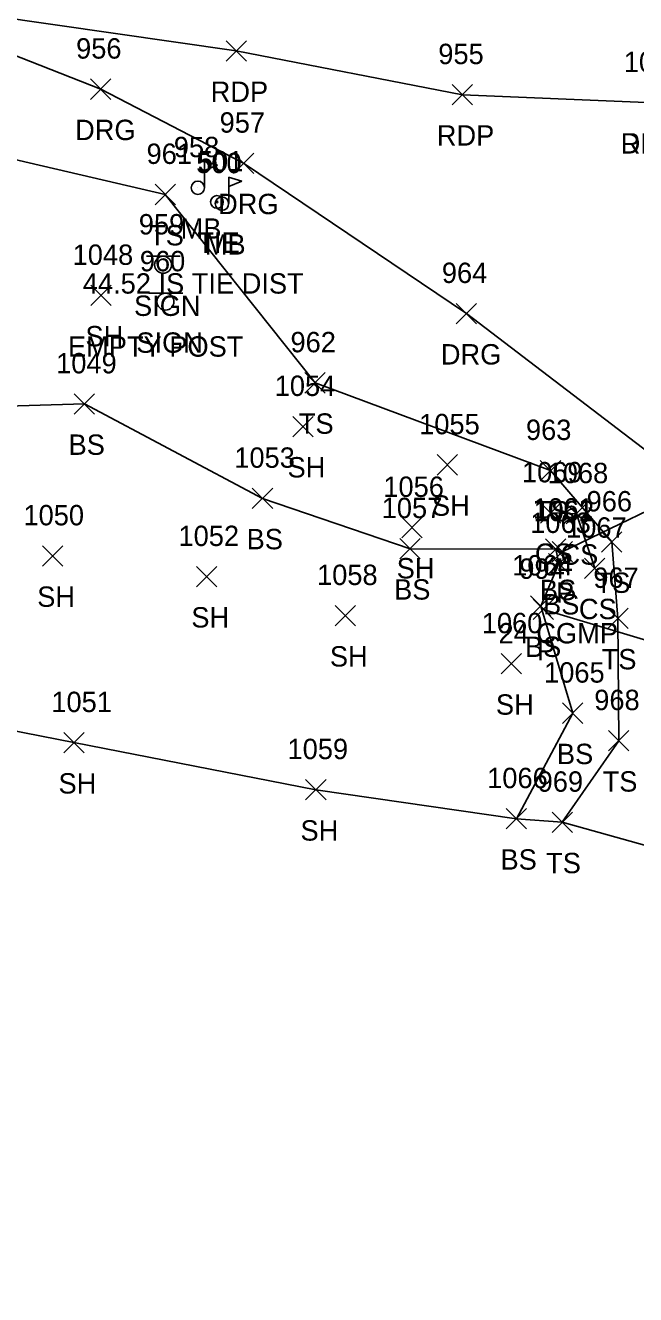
# Model space of a CAD drawing. Extents: x 1679360 to 1685861, y 903420 to 905946.
# Drawn here: x 1679676.5 to 1679736.4, y 903897.6 to 904022.2 of the extents above; entities that cross this region are included whole.
import ezdxf

# ---------------------------------------------------------------- set-up
doc = ezdxf.new("R2010")
doc.units = 0
for name, color, linetype in [('C_A', 7, 'Continuous'), ('C_C', 7, 'Continuous'), ('C_I', 7, 'Continuous'), ('CBP', 7, 'Continuous'), ('D_A', 7, 'Continuous'), ('D_C', 7, 'Continuous'), ('D_I', 7, 'Continuous'), ('D_TIC', 7, 'Continuous'), ('DCP', 7, 'Continuous'), ('L_A', 7, 'Continuous'), ('L_I', 7, 'Continuous'), ('L_TIC', 7, 'Continuous'), ('LELB', 7, 'Continuous'), ('LMB', 7, 'Continuous'), ('LSOGP', 7, 'Continuous'), ('P_A', 7, 'Continuous'), ('P_I', 7, 'Continuous'), ('P_TIC', 7, 'Continuous'), ('PET', 7, 'Continuous'), ('R_A', 7, 'Continuous'), ('R_I', 7, 'Continuous'), ('R_TIC', 7, 'Continuous'), ('RDG', 7, 'Continuous'), ('S_A', 7, 'Continuous'), ('S_C', 7, 'Continuous'), ('S_I', 7, 'Continuous'), ('SSGN', 7, 'Continuous')]:
    doc.layers.add(name, color=color, linetype=linetype)

msp = doc.modelspace()

# ---------------------------------------------------------------- linework, layer by layer
at = {"layer": 'CBP'}
for radius in [0.625, 0.0833]:
    msp.add_circle((1679695.3, 904004.87), radius, dxfattribs=at)
at = {"layer": 'D_TIC'}
for points in [[(1679728.23, 903969.53), (1679730.23, 903971.53)], [(1679730.23, 903969.53), (1679728.23, 903971.53)], [(1679726.37, 903963.87), (1679728.37, 903965.87)], [(1679728.37, 903963.87), (1679726.37, 903965.87)]]:
    msp.add_lwpolyline(points, dxfattribs=at)
at = {"layer": 'DCP'}
for points in [[(1679729.23, 903970.53), (1679771.57, 903990.95)], [(1679765.8, 903953.34), (1679727.37, 903964.87)]]:
    msp.add_lwpolyline(points, dxfattribs=at)
at = {"layer": 'L_TIC'}
for points in [[(1679689.23, 904004.6), (1679691.23, 904006.6)], [(1679691.23, 904004.6), (1679689.23, 904006.6)], [(1679682.91, 903994.69), (1679684.91, 903996.69)], [(1679684.91, 903994.69), (1679682.91, 903996.69)], [(1679703.94, 903986.11), (1679705.94, 903988.11)], [(1679705.94, 903986.11), (1679703.94, 903988.11)], [(1679681.29, 903984.04), (1679683.29, 903986.04)], [(1679683.29, 903984.04), (1679681.29, 903986.04)], [(1679702.75, 903981.82), (1679704.75, 903983.82)], [(1679704.75, 903981.82), (1679702.75, 903983.82)], [(1679716.95, 903978.06), (1679718.95, 903980.06)], [(1679718.95, 903978.06), (1679716.95, 903980.06)], [(1679727.07, 903977.5), (1679729.07, 903979.5)], [(1679729.07, 903977.5), (1679727.07, 903979.5)], [(1679698.78, 903974.77), (1679700.78, 903976.77)], [(1679700.78, 903974.77), (1679698.78, 903976.77)], [(1679727.1, 903973.34), (1679729.1, 903975.34)], [(1679729.1, 903973.34), (1679727.1, 903975.34)], [(1679729.61, 903973.26), (1679731.61, 903975.26)], [(1679731.61, 903973.26), (1679729.61, 903975.26)], [(1679713.48, 903971.91), (1679715.48, 903973.91)], [(1679715.48, 903971.91), (1679713.48, 903973.91)], [(1679733.09, 903970.49), (1679735.09, 903972.49)], [(1679735.09, 903970.49), (1679733.09, 903972.49)], [(1679678.16, 903969.12), (1679680.16, 903971.12)], [(1679680.16, 903969.12), (1679678.16, 903971.12)], [(1679713.27, 903969.83), (1679715.27, 903971.83)], [(1679715.27, 903969.83), (1679713.27, 903971.83)], [(1679727.59, 903969.78), (1679729.59, 903971.78)], [(1679729.59, 903969.78), (1679727.59, 903971.78)], [(1679727.89, 903968.37), (1679729.89, 903970.37)], [(1679729.89, 903968.37), (1679727.89, 903970.37)], [(1679731.42, 903967.91), (1679733.42, 903969.91)], [(1679733.42, 903967.91), (1679731.42, 903969.91)], [(1679693.31, 903967.09), (1679695.31, 903969.09)], [(1679695.31, 903967.09), (1679693.31, 903969.09)], [(1679726.12, 903964.2), (1679728.12, 903966.2)], [(1679728.12, 903964.2), (1679726.12, 903966.2)], [(1679706.91, 903963.26), (1679708.91, 903965.26)], [(1679708.91, 903963.26), (1679706.91, 903965.26)], [(1679733.69, 903962.98), (1679735.69, 903964.98)], [(1679735.69, 903962.98), (1679733.69, 903964.98)], [(1679723.22, 903958.53), (1679725.22, 903960.53)], [(1679725.22, 903958.53), (1679723.22, 903960.53)], [(1679729.26, 903953.68), (1679731.26, 903955.68)], [(1679731.26, 903953.68), (1679729.26, 903955.68)], [(1679680.25, 903950.79), (1679682.25, 903952.79)], [(1679682.25, 903950.79), (1679680.25, 903952.79)], [(1679733.78, 903950.98), (1679735.78, 903952.98)], [(1679735.78, 903950.98), (1679733.78, 903952.98)], [(1679704.02, 903946.17), (1679706.02, 903948.17)], [(1679706.02, 903946.17), (1679704.02, 903948.17)], [(1679723.72, 903943.32), (1679725.72, 903945.32)], [(1679725.72, 903943.32), (1679723.72, 903945.32)], [(1679728.23, 903942.97), (1679730.23, 903944.97)], [(1679730.23, 903942.97), (1679728.23, 903944.97)]]:
    msp.add_lwpolyline(points, dxfattribs=at)
at = {"layer": 'LELB'}
for points in [[(1679463.5, 904033.6), (1679493.73, 904031.16), (1679533.11, 904028.25), (1679569.66, 904025.54), (1679615.59, 904019.51), (1679642.06, 904019.99), (1679667.28, 904010.94), (1679690.23, 904005.6), (1679704.94, 903987.11), (1679728.07, 903978.5), (1679734.09, 903971.49), (1679734.69, 903963.98), (1679734.78, 903951.98), (1679729.23, 903943.97)], [(1679461.4, 903999.1), (1679511.25, 903995.13), (1679547.07, 903992.49), (1679589.93, 903992.87), (1679619.36, 903991.19), (1679660.51, 903984.39), (1679682.29, 903985.04), (1679699.78, 903975.77), (1679714.27, 903970.83), (1679728.59, 903970.78), (1679728.89, 903969.37), (1679727.12, 903965.2), (1679730.26, 903954.68), (1679724.72, 903944.32)], [(1679732.42, 903968.91), (1679730.61, 903974.26), (1679728.1, 903974.34)]]:
    msp.add_lwpolyline(points, dxfattribs=at)
at = {"layer": 'LMB'}
for p, q in [((1679694.08, 904008.86), (1679695.37, 904008.48)), ((1679694.09, 904006.27), (1679694.08, 904008.86)), ((1679694.08, 904007.96), (1679695.37, 904008.47)), ((1679696.45, 904007.3), (1679697.74, 904006.92)), ((1679696.46, 904004.71), (1679696.46, 904007.3)), ((1679693.43, 904006.26), (1679693.43, 904006.26)), ((1679696.46, 904006.4), (1679697.74, 904006.91)), ((1679695.8, 904004.7), (1679695.8, 904004.7))]:
    msp.add_line(p, q, dxfattribs=at)
for centre in [(1679693.43, 904006.26), (1679695.8, 904004.7)]:
    msp.add_circle(centre, 0.656, dxfattribs=at)
at = {"layer": 'LSOGP'}
msp.add_lwpolyline([(1679658.66, 903956.21), (1679681.25, 903951.79), (1679705.02, 903947.17), (1679724.72, 903944.32), (1679729.23, 903943.97), (1679740.35, 903940.87), (1679752.19, 903934.97), (1679756.03, 903933.83), (1679765.66, 903928.78), (1679788.58, 903897.6), (1679796.73, 903913.04), (1679805.44, 903927.25), (1679808.63, 903929.84), (1679809.97, 903931.78), (1679849.71, 903926.51)], dxfattribs=at)
at = {"layer": 'P_TIC'}
for points in [[(1679696.2, 904018.69), (1679698.2, 904020.69)], [(1679698.2, 904018.69), (1679696.2, 904020.69)], [(1679718.42, 904014.4), (1679720.42, 904016.4)], [(1679720.42, 904014.4), (1679718.42, 904016.4)]]:
    msp.add_lwpolyline(points, dxfattribs=at)
at = {"layer": 'PET'}
msp.add_lwpolyline([(1679464.45, 904041.77), (1679494.85, 904039.78), (1679533.66, 904036.86), (1679564.76, 904034.75), (1679595.94, 904030.8), (1679627.79, 904028.13), (1679661.16, 904024.92), (1679697.2, 904019.69), (1679719.42, 904015.4), (1679737.48, 904014.62), (1679744.58, 904019.77), (1679770.86, 904017.76), (1679789.63, 904016.53)], dxfattribs=at)
at = {"layer": 'R_TIC'}
for points in [[(1679682.89, 904014.94), (1679684.89, 904016.94)], [(1679684.89, 904014.94), (1679682.89, 904016.94)], [(1679696.93, 904007.67), (1679698.93, 904009.67)], [(1679698.93, 904007.67), (1679696.93, 904009.67)], [(1679718.81, 903992.91), (1679720.81, 903994.91)], [(1679720.81, 903992.91), (1679718.81, 903994.91)]]:
    msp.add_lwpolyline(points, dxfattribs=at)
at = {"layer": 'RDG'}
msp.add_lwpolyline([(1679661.16, 904024.92), (1679683.89, 904015.94), (1679697.93, 904008.67), (1679719.81, 903993.91), (1679739.61, 903978.84), (1679766.51, 903961.28), (1679785.72, 903950.36), (1679809.97, 903931.78)], dxfattribs=at)
at = {"layer": 'SSGN'}
for p, q in [((1679688.37, 903999.54), (1679691.7, 903999.54)), ((1679690.02, 903998.7), (1679690.02, 903998.7)), ((1679688.6, 903995.92), (1679691.94, 903995.92)), ((1679690.25, 903995.08), (1679690.25, 903995.08))]:
    msp.add_line(p, q, dxfattribs=at)
for centre in [(1679690.02, 903998.7), (1679690.25, 903995.08)]:
    msp.add_circle(centre, 0.833, dxfattribs=at)

# ---------------------------------------------------------------- texts
at = {"layer": 'C_A'}
msp.add_text('TIE', height=2, dxfattribs=at).set_placement((1679693.38, 903999.87))
at = {"layer": 'C_C'}
msp.add_text('44.52 IS TIE DIST', height=2, dxfattribs=at).set_placement((1679682.13, 903995.87))
at = {"layer": 'C_I'}
msp.add_text('501', height=2, dxfattribs=at).set_placement((1679693.43, 904007.87))
at = {"layer": 'D_A'}
for p in [(1679728.61, 903965.53), (1679726.75, 903959.87)]:
    msp.add_text('P', height=2, dxfattribs=at).set_placement(p)
at = {"layer": 'D_C'}
msp.add_text('24 CGMP', height=2, dxfattribs=at).set_placement((1679722.96, 903961.53))
at = {"layer": 'D_I'}
for s, p in [('1062', (1679726.41, 903973.53)), ('994', (1679725.01, 903967.87))]:
    msp.add_text(s, height=2, dxfattribs=at).set_placement(p)
at = {"layer": 'L_A'}
for s, p in [('TS', (1679688.64, 904000.6)), ('MB', (1679691.74, 904001.26)), ('MB', (1679694.11, 903999.7)), ('SH', (1679682.39, 903990.69)), ('TS', (1679703.35, 903982.11)), ('BS', (1679680.73, 903980.04)), ('SH', (1679702.24, 903977.82)), ('SH', (1679716.43, 903974.06)), ('TS', (1679726.48, 903973.5)), ('BS', (1679698.22, 903970.77)), ('CS', (1679726.54, 903969.34)), ('CS', (1679729.05, 903969.26)), ('SH', (1679712.96, 903967.91)), ('BS', (1679712.71, 903965.83)), ('BS', (1679727.03, 903965.78)), ('TS', (1679732.5, 903966.49)), ('SH', (1679677.65, 903965.12)), ('BS', (1679727.34, 903964.37)), ('SH', (1679692.79, 903963.09)), ('CS', (1679730.86, 903963.91)), ('SH', (1679706.4, 903959.26)), ('BS', (1679725.56, 903960.2)), ('TS', (1679733.1, 903958.98)), ('SH', (1679722.71, 903954.53)), ('BS', (1679728.7, 903949.68)), ('SH', (1679679.74, 903946.79)), ('TS', (1679733.19, 903946.98)), ('SH', (1679703.51, 903942.17)), ('BS', (1679723.16, 903939.32)), ('TS', (1679727.64, 903938.97))]:
    msp.add_text(s, height=2, dxfattribs=at).set_placement(p)
at = {"layer": 'L_I'}
for s, p in [('958', (1679691.07, 904009.26)), ('961', (1679688.39, 904008.6)), ('500', (1679693.27, 904007.7)), ('1048', (1679681.13, 903998.69)), ('962', (1679702.53, 903990.11)), ('1049', (1679679.51, 903988.04)), ('1054', (1679700.98, 903985.82)), ('1055', (1679715.17, 903982.06)), ('963', (1679725.66, 903981.5)), ('1053', (1679697.01, 903978.77)), ('1069', (1679725.27, 903977.34)), ('1068', (1679727.79, 903977.26)), ('1056', (1679711.65, 903975.91)), ('966', (1679731.62, 903974.49)), ('1050', (1679676.3, 903973.12)), ('1057', (1679711.49, 903973.83)), ('1061', (1679726.34, 903973.78)), ('1063', (1679726.08, 903972.37)), ('1067', (1679729.6, 903971.91)), ('1052', (1679691.53, 903971.09)), ('1064', (1679724.31, 903968.2)), ('1058', (1679705.14, 903967.26)), ('967', (1679732.28, 903966.98)), ('1060', (1679721.32, 903962.53)), ('1065', (1679727.44, 903957.68)), ('1051', (1679679.04, 903954.79)), ('968', (1679732.37, 903954.98)), ('1059', (1679702.24, 903950.17)), ('1066', (1679721.85, 903947.32)), ('969', (1679726.81, 903946.97))]:
    msp.add_text(s, height=2, dxfattribs=at).set_placement(p)
at = {"layer": 'P_A'}
for p in [(1679694.69, 904014.69), (1679716.9, 904010.4), (1679734.96, 904009.62)]:
    msp.add_text('RDP', height=2, dxfattribs=at).set_placement(p)
at = {"layer": 'P_I'}
for s, p in [('955', (1679717.05, 904018.4)), ('1014', (1679735.27, 904017.62))]:
    msp.add_text(s, height=2, dxfattribs=at).set_placement(p)
at = {"layer": 'R_A'}
for p in [(1679681.37, 904010.94), (1679734.96, 904009.62), (1679695.42, 904003.67), (1679717.3, 903988.91)]:
    msp.add_text('DRG', height=2, dxfattribs=at).set_placement(p)
at = {"layer": 'R_I'}
for s, p in [('956', (1679681.47, 904018.94)), ('1014', (1679735.27, 904017.62)), ('957', (1679695.57, 904011.67)), ('964', (1679717.4, 903996.91))]:
    msp.add_text(s, height=2, dxfattribs=at).set_placement(p)
at = {"layer": 'S_A'}
for p in [(1679687.16, 903993.68), (1679687.39, 903990.06)]:
    msp.add_text('SIGN', height=2, dxfattribs=at).set_placement(p)
at = {"layer": 'S_C'}
msp.add_text('EMPTY POST', height=2, dxfattribs=at).set_placement((1679680.67, 903989.68))
at = {"layer": 'S_I'}
for s, p in [('959', (1679687.63, 904001.68)), ('960', (1679687.73, 903998.06))]:
    msp.add_text(s, height=2, dxfattribs=at).set_placement(p)

doc.saveas('drawing.dxf')
